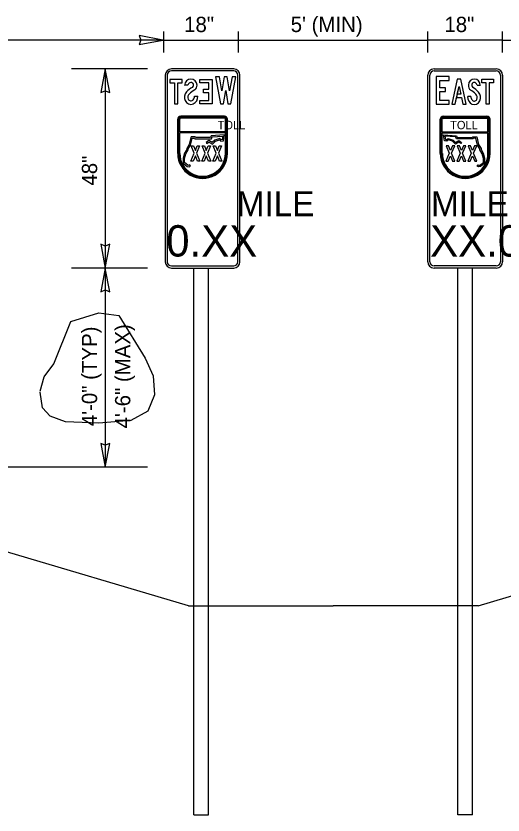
# Model space of a CAD drawing. Extents: x 56768 to 57406, y 11696 to 12105.
# Drawn here: x 56946.4 to 57035.7, y 11762.4 to 11908.9 of the extents above; entities that cross this region are included whole.
import ezdxf

# ---------------------------------------------------------------- set-up
doc = ezdxf.new("R2010")
doc.units = 0
for name, color, linetype in [('1', 7, 'Continuous'), ('52', 7, 'Continuous'), ('62', 7, 'Continuous'), ('DimLines_dp', 7, 'Continuous'), ('SignPanel', 7, 'Continuous'), ('XSGrdLine_ex', 7, 'Continuous')]:
    doc.layers.add(name, color=color, linetype=linetype)

msp = doc.modelspace()

# ---------------------------------------------------------------- linework, layer by layer
at = {"layer": '1'}
for p, q in [((56979.04, 11800.77), (56979.04, 11862.72)), ((56981.7, 11800.77), (56981.7, 11862.72)), ((57027.41, 11800.77), (57027.41, 11862.72)), ((57030.07, 11800.77), (57030.07, 11862.72)), ((56979.04, 11762.45), (56979.04, 11800.77)), ((56981.7, 11762.45), (56981.7, 11800.77)), ((57027.41, 11762.45), (57027.41, 11800.77)), ((57030.07, 11762.45), (57030.07, 11800.77)), ((56979.04, 11762.45), (56981.7, 11762.45)), ((57030.07, 11762.45), (57027.41, 11762.45))]:
    msp.add_line(p, q, dxfattribs=at)
at = {"layer": '52'}
msp.add_line((56970.53, 11826.22), (56892.41, 11826.22), dxfattribs=at)
at = {"layer": '62'}
msp.add_lwpolyline([(56950.87, 11840.16), (56951.57, 11842.76), (56953.37, 11845.17), (56956.48, 11852.92), (56961.58, 11854.52), (56965.28, 11854.02), (56970.08, 11846.17), (56971.58, 11842.96), (56971.78, 11839.46), (56970.58, 11836.46), (56967.48, 11834.75), (56961.58, 11834.25), (56955.47, 11834.55), (56952.67, 11835.56), (56951.27, 11837.06), (56950.87, 11839.96)], dxfattribs=at)
at = {"layer": 'DimLines_dp'}
for p, q in [((56973.53, 11902.22), (56973.53, 11906.05)), ((56987.21, 11902.22), (56987.21, 11906.05)), ((57021.89, 11902.22), (57021.89, 11906.05)), ((57035.58, 11902.22), (57035.58, 11906.05)), ((56973.53, 11904.5), (56892.41, 11904.5)), ((56973.34, 11904.5), (56968.99, 11905.34)), ((56968.99, 11905.34), (56969.32, 11904.5)), ((56969.32, 11904.5), (56968.99, 11903.69)), ((56968.99, 11903.69), (56973.34, 11904.5)), ((56973.53, 11904.5), (56987.21, 11904.5)), ((56987.21, 11904.5), (57021.89, 11904.5)), ((57035.58, 11904.5), (57021.89, 11904.5)), ((57035.58, 11904.5), (57116.7, 11904.5)), ((56970.53, 11899.22), (56956.6, 11899.22)), ((56962.78, 11899.22), (56961.94, 11894.87)), ((56962.78, 11899.22), (56962.78, 11862.72)), ((56963.59, 11894.87), (56962.78, 11899.22)), ((56961.94, 11894.87), (56962.78, 11895.2)), ((56962.78, 11895.2), (56963.59, 11894.87)), ((56962.78, 11866.74), (56961.97, 11867.07)), ((56961.97, 11867.07), (56962.78, 11862.72)), ((56962.78, 11866.74), (56961.97, 11867.07)), ((56961.97, 11867.07), (56962.78, 11862.72)), ((56962.78, 11862.72), (56963.62, 11867.07)), ((56963.62, 11867.07), (56962.78, 11866.74)), ((56962.78, 11862.72), (56963.62, 11867.07)), ((56963.62, 11867.07), (56962.78, 11866.74)), ((56970.53, 11862.72), (56956.6, 11862.72)), ((56962.78, 11862.72), (56961.94, 11858.37)), ((56962.78, 11862.72), (56962.78, 11826.22)), ((56963.59, 11858.37), (56962.78, 11862.72)), ((56961.94, 11858.37), (56962.78, 11858.7)), ((56962.78, 11858.7), (56963.59, 11858.37)), ((56962.78, 11830.24), (56961.97, 11830.57)), ((56961.97, 11830.57), (56962.78, 11826.22)), ((56962.78, 11826.22), (56963.62, 11830.57)), ((56963.62, 11830.57), (56962.78, 11830.24))]:
    msp.add_line(p, q, dxfattribs=at)
at = {"layer": 'SignPanel'}
for p, q in [((56977.92, 11896.21), (56977.31, 11896.21)), ((56977.92, 11896.21), (56977.31, 11896.21)), ((56977.92, 11896.21), (56977.31, 11896.21)), ((57030.93, 11896.21), (57031.52, 11896.21)), ((57030.93, 11896.21), (57031.52, 11896.21)), ((57030.93, 11896.21), (57031.52, 11896.21)), ((56979.12, 11894.2), (56979.74, 11894.2)), ((56979.12, 11894.2), (56979.74, 11894.2)), ((56979.12, 11894.2), (56979.74, 11894.2)), ((57029.79, 11894.17), (57029.2, 11894.17)), ((57029.79, 11894.17), (57029.2, 11894.17)), ((57029.79, 11894.17), (57029.2, 11894.17)), ((56976.05, 11883.7), (56976.05, 11889.98)), ((56976.25, 11883.7), (56976.25, 11889.98)), ((56976.44, 11887.7), (56976.44, 11889.98)), ((56984.61, 11890.55), (56976.62, 11890.55)), ((56984.61, 11890.36), (56976.62, 11890.36)), ((56984.61, 11890.17), (56976.62, 11890.17)), ((56984.8, 11887.7), (56984.8, 11889.98)), ((56984.99, 11883.7), (56984.99, 11889.98)), ((56985.18, 11883.7), (56985.18, 11889.98)), ((57024.18, 11883.7), (57024.18, 11889.98)), ((57024.37, 11883.7), (57024.37, 11889.98)), ((57024.55, 11887.7), (57024.55, 11889.98)), ((57024.75, 11890.55), (57032.73, 11890.55)), ((57024.75, 11890.36), (57032.73, 11890.36)), ((57024.75, 11890.17), (57032.73, 11890.17)), ((57032.92, 11887.7), (57032.92, 11889.98)), ((57033.11, 11883.7), (57033.11, 11889.98)), ((57033.3, 11883.7), (57033.3, 11889.98)), ((56984.8, 11887.7), (56976.44, 11887.7)), ((56976.44, 11883.7), (56976.44, 11887.51)), ((56984.8, 11887.51), (56976.44, 11887.51)), ((56978.5, 11886.77), (56978.17, 11885.34)), ((56979.24, 11886.77), (56978.5, 11886.77)), ((56979.34, 11886.62), (56979.24, 11886.77)), ((56982.07, 11886.62), (56979.34, 11886.62)), ((56982.21, 11886.96), (56982.07, 11886.62)), ((56984.59, 11887.14), (56982.21, 11886.96)), ((56982.23, 11886.39), (56982.37, 11886.74)), ((56982.37, 11886.74), (56984.31, 11886.89)), ((56983.33, 11886.8), (56983.33, 11886.8)), ((56984.31, 11886.89), (56984.22, 11886.26)), ((56984.42, 11886.05), (56984.59, 11887.14)), ((56984.8, 11883.7), (56984.8, 11887.51)), ((57024.55, 11887.7), (57032.92, 11887.7)), ((57024.55, 11883.7), (57024.55, 11887.51)), ((57024.55, 11887.51), (57032.92, 11887.51)), ((57024.94, 11886.05), (57024.77, 11887.14)), ((57024.77, 11887.14), (57027.15, 11886.96)), ((57026.99, 11886.74), (57025.04, 11886.89)), ((57025.04, 11886.89), (57025.14, 11886.26)), ((57026.03, 11886.8), (57026.03, 11886.8)), ((57027.13, 11886.39), (57026.99, 11886.74)), ((57027.15, 11886.96), (57027.28, 11886.62)), ((57027.28, 11886.62), (57030.01, 11886.62)), ((57030.01, 11886.62), (57030.12, 11886.77)), ((57030.12, 11886.77), (57030.85, 11886.77)), ((57030.85, 11886.77), (57031.18, 11885.34)), ((57032.92, 11883.7), (57032.92, 11887.51)), ((56978.17, 11885.34), (56977.72, 11884.61)), ((56977.95, 11884.54), (56978.39, 11885.25)), ((56978.39, 11885.25), (56978.69, 11886.54)), ((56978.69, 11886.54), (56979.12, 11886.54)), ((56979.12, 11886.54), (56979.22, 11886.39)), ((56979.22, 11886.39), (56982.23, 11886.39)), ((56981.78, 11886.09), (56981.28, 11885.75)), ((56981.28, 11885.75), (56981.41, 11885.56)), ((56981.41, 11885.56), (56981.79, 11885.82)), ((56982.39, 11885.73), (56981.78, 11886.09)), ((56981.79, 11885.82), (56982.42, 11885.45)), ((56982.84, 11886.15), (56982.39, 11885.73)), ((56982.42, 11885.45), (56982.96, 11885.95)), ((56983.76, 11886.45), (56982.84, 11886.15)), ((56982.96, 11885.95), (56983.71, 11886.19)), ((56983.71, 11886.19), (56983.96, 11886)), ((56984.03, 11886.24), (56983.76, 11886.45)), ((56983.96, 11886), (56984.42, 11886.05)), ((56984.22, 11886.26), (56984.03, 11886.24)), ((57025.39, 11886), (57024.94, 11886.05)), ((57025.14, 11886.26), (57025.33, 11886.24)), ((57025.33, 11886.24), (57025.6, 11886.45)), ((57025.64, 11886.19), (57025.39, 11886)), ((57025.6, 11886.45), (57026.52, 11886.15)), ((57026.4, 11885.95), (57025.64, 11886.19)), ((57026.94, 11885.45), (57026.4, 11885.95)), ((57026.52, 11886.15), (57026.97, 11885.73)), ((57027.57, 11885.82), (57026.94, 11885.45)), ((57026.97, 11885.73), (57027.58, 11886.09)), ((57030.14, 11886.39), (57027.13, 11886.39)), ((57027.95, 11885.56), (57027.57, 11885.82)), ((57027.58, 11886.09), (57028.08, 11885.75)), ((57028.08, 11885.75), (57027.95, 11885.56)), ((57030.24, 11886.54), (57030.14, 11886.39)), ((57030.67, 11886.54), (57030.24, 11886.54)), ((57030.97, 11885.25), (57030.67, 11886.54)), ((57031.41, 11884.54), (57030.97, 11885.25)), ((57031.18, 11885.34), (57031.64, 11884.61)), ((56977.31, 11883.75), (56977.06, 11882.83)), ((56977.29, 11882.8), (56977.52, 11883.66)), ((56977.72, 11884.43), (56977.31, 11883.75)), ((56977.52, 11883.66), (56977.95, 11884.36)), ((56977.72, 11884.61), (56977.72, 11884.43)), ((56977.95, 11884.36), (56977.95, 11884.54)), ((57031.41, 11884.36), (57031.41, 11884.54)), ((57031.83, 11883.66), (57031.41, 11884.36)), ((57031.64, 11884.61), (57031.64, 11884.43)), ((57031.64, 11884.43), (57032.05, 11883.75)), ((57032.07, 11882.8), (57031.83, 11883.66)), ((57032.05, 11883.75), (57032.3, 11882.83)), ((56977.06, 11882.83), (56977.06, 11881.97)), ((56977.29, 11882.07), (56977.29, 11882.8)), ((57032.07, 11882.07), (57032.07, 11882.8)), ((57032.3, 11882.83), (57032.3, 11881.97)), ((56977.06, 11881.97), (56977.81, 11881.35)), ((56977.91, 11881.56), (56977.29, 11882.07)), ((56977.81, 11881.35), (56978.17, 11881.26)), ((56978.12, 11881.51), (56977.91, 11881.56)), ((56978.26, 11881.61), (56978.12, 11881.51)), ((56978.17, 11881.26), (56978.39, 11881.42)), ((56978.39, 11881.42), (56978.26, 11881.61)), ((57030.96, 11881.42), (57031.09, 11881.61)), ((57031.19, 11881.26), (57030.96, 11881.42)), ((57031.09, 11881.61), (57031.24, 11881.51)), ((57031.55, 11881.35), (57031.19, 11881.26)), ((57031.24, 11881.51), (57031.44, 11881.56)), ((57031.44, 11881.56), (57032.07, 11882.07)), ((57032.3, 11881.97), (57031.55, 11881.35))]:
    msp.add_line(p, q, dxfattribs=at)
for points in [[(56986.32, 11899.22), (56974.91, 11899.22)], [(56986.32, 11898.84), (56974.91, 11898.84)], [(57023.03, 11899.22), (57034.44, 11899.22)], [(57023.03, 11898.84), (57034.44, 11898.84)], [(56973.77, 11898.08), (56973.77, 11863.86)], [(56974.15, 11898.08), (56974.15, 11863.86)], [(56987.08, 11863.86), (56987.08, 11898.08)], [(56987.46, 11863.86), (56987.46, 11898.08)], [(57021.89, 11863.86), (57021.89, 11898.08)], [(57022.27, 11863.86), (57022.27, 11898.08)], [(57035.2, 11898.08), (57035.2, 11863.86)], [(57035.58, 11898.08), (57035.58, 11863.86)], [(56974.91, 11863.1), (56986.32, 11863.1)], [(56974.91, 11862.72), (56986.32, 11862.72)], [(57034.44, 11863.1), (57023.03, 11863.1)], [(57034.44, 11862.72), (57023.03, 11862.72)]]:
    msp.add_lwpolyline(points, dxfattribs=at)
for points in [[(56976.06, 11896.66), (56976.88, 11896.66), (56976.88, 11897.29), (56974.62, 11897.29), (56974.62, 11896.66), (56975.44, 11896.66), (56975.44, 11892.79), (56976.06, 11892.79)], [(56976.06, 11896.66), (56976.88, 11896.66), (56976.88, 11897.29), (56974.62, 11897.29), (56974.62, 11896.66), (56975.44, 11896.66), (56975.44, 11892.79), (56976.06, 11892.79)], [(56976.06, 11896.66), (56976.88, 11896.66), (56976.88, 11897.29), (56974.62, 11897.29), (56974.62, 11896.66), (56975.44, 11896.66), (56975.44, 11892.79), (56976.06, 11892.79)], [(56981.77, 11893.42), (56981.77, 11894.86), (56980.8, 11894.86), (56980.8, 11895.49), (56981.77, 11895.49), (56981.77, 11896.66), (56980.13, 11896.66), (56980.13, 11897.29), (56982.39, 11897.29), (56982.39, 11892.79), (56980.13, 11892.79), (56980.13, 11893.42)], [(56981.77, 11893.42), (56981.77, 11894.86), (56980.8, 11894.86), (56980.8, 11895.49), (56981.77, 11895.49), (56981.77, 11896.66), (56980.13, 11896.66), (56980.13, 11897.29), (56982.39, 11897.29), (56982.39, 11892.79), (56980.13, 11892.79), (56980.13, 11893.42)], [(56981.77, 11893.42), (56981.77, 11894.86), (56980.8, 11894.86), (56980.8, 11895.49), (56981.77, 11895.49), (56981.77, 11896.66), (56980.13, 11896.66), (56980.13, 11897.29), (56982.39, 11897.29), (56982.39, 11892.79), (56980.13, 11892.79), (56980.13, 11893.42)], [(56985.55, 11895.18), (56985.15, 11897.74), (56984.55, 11897.74), (56984.14, 11895.18), (56983.69, 11897.74), (56982.99, 11897.74), (56983.87, 11892.79), (56984.46, 11892.79), (56984.85, 11895.27), (56985.24, 11892.79), (56985.82, 11892.79), (56986.7, 11897.74), (56986.01, 11897.74)], [(56985.55, 11895.18), (56985.15, 11897.74), (56984.55, 11897.74), (56984.14, 11895.18), (56983.69, 11897.74), (56982.99, 11897.74), (56983.87, 11892.79), (56984.46, 11892.79), (56984.85, 11895.27), (56985.24, 11892.79), (56985.82, 11892.79), (56986.7, 11897.74), (56986.01, 11897.74)], [(56985.55, 11895.18), (56985.15, 11897.74), (56984.55, 11897.74), (56984.14, 11895.18), (56983.69, 11897.74), (56982.99, 11897.74), (56983.87, 11892.79), (56984.46, 11892.79), (56984.85, 11895.27), (56985.24, 11892.79), (56985.82, 11892.79), (56986.7, 11897.74), (56986.01, 11897.74)], [(57024.1, 11893.44), (57024.1, 11895.07), (57025.12, 11895.07), (57025.12, 11895.77), (57024.1, 11895.77), (57024.1, 11897.09), (57025.82, 11897.09), (57025.82, 11897.8), (57023.45, 11897.8), (57023.45, 11892.74), (57025.82, 11892.74), (57025.82, 11893.44)], [(57024.1, 11893.44), (57024.1, 11895.07), (57025.12, 11895.07), (57025.12, 11895.77), (57024.1, 11895.77), (57024.1, 11897.09), (57025.82, 11897.09), (57025.82, 11897.8), (57023.45, 11897.8), (57023.45, 11892.74), (57025.82, 11892.74), (57025.82, 11893.44)], [(57024.1, 11893.44), (57024.1, 11895.07), (57025.12, 11895.07), (57025.12, 11895.77), (57024.1, 11895.77), (57024.1, 11897.09), (57025.82, 11897.09), (57025.82, 11897.8), (57023.45, 11897.8), (57023.45, 11892.74), (57025.82, 11892.74), (57025.82, 11893.44)], [(57028.07, 11893.96), (57028.34, 11892.74), (57028.95, 11892.74), (57027.93, 11897.31), (57027.29, 11897.31), (57026.27, 11892.74), (57026.88, 11892.74), (57027.15, 11893.96)], [(57027.3, 11894.6), (57027.15, 11893.96), (57028.07, 11893.96), (57028.34, 11892.74), (57028.95, 11892.74), (57027.93, 11897.31), (57027.29, 11897.31), (57026.27, 11892.74), (57026.88, 11892.74), (57027.61, 11896.01), (57027.92, 11894.6)], [(57027.3, 11894.6), (57027.15, 11893.96), (57028.07, 11893.96), (57028.34, 11892.74), (57028.95, 11892.74), (57027.93, 11897.31), (57027.29, 11897.31), (57026.27, 11892.74), (57026.88, 11892.74), (57027.61, 11896.01), (57027.92, 11894.6)], [(57032.58, 11896.67), (57031.8, 11896.67), (57031.8, 11897.31), (57033.94, 11897.31), (57033.94, 11896.67), (57033.16, 11896.67), (57033.16, 11892.74), (57032.58, 11892.74)], [(57032.58, 11896.67), (57031.8, 11896.67), (57031.8, 11897.31), (57033.94, 11897.31), (57033.94, 11896.67), (57033.16, 11896.67), (57033.16, 11892.74), (57032.58, 11892.74)], [(57032.58, 11896.67), (57031.8, 11896.67), (57031.8, 11897.31), (57033.94, 11897.31), (57033.94, 11896.67), (57033.16, 11896.67), (57033.16, 11892.74), (57032.58, 11892.74)], [(57027.61, 11896.01), (57027.92, 11894.6), (57027.3, 11894.6)], [(56979.7, 11882.29), (56979.29, 11883.26), (56978.88, 11882.29), (56978.45, 11882.29), (56979.07, 11883.77), (56978.5, 11885.14), (56978.93, 11885.14), (56979.29, 11884.28), (56979.65, 11885.14), (56980.07, 11885.14), (56979.5, 11883.77), (56980.12, 11882.29)], [(56981.71, 11882.29), (56981.3, 11883.26), (56980.9, 11882.29), (56980.47, 11882.29), (56981.09, 11883.77), (56980.52, 11885.14), (56980.95, 11885.14), (56981.3, 11884.28), (56981.66, 11885.14), (56982.09, 11885.14), (56981.52, 11883.77), (56982.14, 11882.29)], [(56983.73, 11882.29), (56983.32, 11883.26), (56982.91, 11882.29), (56982.48, 11882.29), (56983.11, 11883.77), (56982.53, 11885.14), (56982.96, 11885.14), (56983.32, 11884.28), (56983.68, 11885.14), (56984.11, 11885.14), (56983.53, 11883.77), (56984.16, 11882.29)], [(57025.63, 11882.29), (57026.04, 11883.26), (57026.44, 11882.29), (57026.87, 11882.29), (57026.25, 11883.77), (57026.82, 11885.14), (57026.39, 11885.14), (57026.04, 11884.28), (57025.68, 11885.14), (57025.25, 11885.14), (57025.82, 11883.77), (57025.2, 11882.29)], [(57027.64, 11882.29), (57028.05, 11883.26), (57028.46, 11882.29), (57028.89, 11882.29), (57028.27, 11883.77), (57028.84, 11885.14), (57028.41, 11885.14), (57028.05, 11884.28), (57027.69, 11885.14), (57027.27, 11885.14), (57027.84, 11883.77), (57027.22, 11882.29)], [(57029.66, 11882.29), (57030.07, 11883.26), (57030.48, 11882.29), (57030.9, 11882.29), (57030.28, 11883.77), (57030.85, 11885.14), (57030.43, 11885.14), (57030.07, 11884.28), (57029.71, 11885.14), (57029.28, 11885.14), (57029.85, 11883.77), (57029.23, 11882.29)]]:
    msp.add_lwpolyline(points, close=True, dxfattribs=at)
for centre, radius, start, end in [((56974.91, 11898.08), 1.14, 90, 180), ((56974.91, 11898.08), 0.76, 90, 180), ((56986.32, 11898.08), 1.14, 0, 90), ((56986.32, 11898.08), 0.76, 0, 90), ((57023.03, 11898.08), 1.14, 90, 180), ((57023.03, 11898.08), 0.76, 90, 180), ((57034.44, 11898.08), 1.14, 0, 90), ((57034.44, 11898.08), 0.76, 0, 90), ((56974.91, 11863.86), 1.14, 180, 270), ((56974.91, 11863.86), 0.76, 180, 270), ((56986.32, 11863.86), 1.14, 270, 0), ((56986.32, 11863.86), 0.76, 270, 0), ((57023.03, 11863.86), 1.14, 180, 270), ((57023.03, 11863.86), 0.76, 180, 270), ((57034.44, 11863.86), 1.14, 270, 360), ((57034.44, 11863.86), 0.76, 270, 360)]:
    msp.add_arc(centre, radius, start, end, dxfattribs=at)
for centre, major_axis, ratio, start_param, end_param in [((56978.46, 11896.18), (0, -1.17), 0.981197, 1.634182, 4.688511), ((56978.46, 11896.18), (0, -1.17), 0.981197, 1.634182, 4.688511), ((56978.46, 11896.18), (0, -1.17), 0.981197, 1.634182, 4.688511), ((57030.42, 11896.18), (0, 1.19), 0.91923, 4.736267, 7.790596), ((57030.42, 11896.18), (0, 1.19), 0.91923, 4.736267, 7.790596), ((57030.42, 11896.18), (0, 1.19), 0.91923, 4.736267, 7.790596), ((56980.77, 11892.05), (0, -4.32), 0.981197, 3.642536, 3.961892), ((56980.77, 11892.05), (0, -4.32), 0.981197, 3.642536, 3.961892), ((56980.77, 11892.05), (0, -4.32), 0.981197, 3.642536, 3.961892), ((56978.46, 11896.17), (0, -0.55), 0.981197, 2.28404, 4.637874), ((56978.46, 11896.17), (0, -0.55), 0.981197, 2.28404, 4.637874), ((56978.46, 11896.17), (0, -0.55), 0.981197, 2.28404, 4.637874), ((56981.31, 11891.36), (0, -4.56), 0.981197, 3.63779, 3.909641), ((56981.31, 11891.36), (0, -4.56), 0.981197, 3.63779, 3.909641), ((56981.31, 11891.36), (0, -4.56), 0.981197, 3.63779, 3.909641), ((56978.53, 11896.24), (0, -0.453), 0.981197, 0.484634, 2.267813), ((56978.53, 11896.24), (0, -0.453), 0.981197, 0.484634, 2.267813), ((56978.53, 11896.24), (0, -0.453), 0.981197, 0.484634, 2.267813), ((56978.57, 11896.22), (0, -1.05), 0.981197, 0.629826, 1.606762), ((56978.57, 11896.22), (0, -1.05), 0.981197, 0.629826, 1.606762), ((56978.57, 11896.22), (0, -1.05), 0.981197, 0.629826, 1.606762), ((57030.31, 11896.22), (0, 1.07), 0.91923, 1.534831, 2.511766), ((57030.31, 11896.22), (0, 1.07), 0.91923, 1.534831, 2.511766), ((57030.31, 11896.22), (0, 1.07), 0.91923, 1.534831, 2.511766), ((57027.71, 11891.28), (0, 4.63), 0.91923, 5.515137, 5.786988), ((57027.71, 11891.28), (0, 4.63), 0.91923, 5.515137, 5.786988), ((57027.71, 11891.28), (0, 4.63), 0.91923, 5.515137, 5.786988), ((57030.35, 11896.24), (0, 0.46), 0.91923, 0.87378, 2.656959), ((57030.35, 11896.24), (0, 0.46), 0.91923, 0.87378, 2.656959), ((57030.35, 11896.24), (0, 0.46), 0.91923, 0.87378, 2.656959), ((57030.42, 11896.17), (0, 0.558), 0.91923, 4.786904, 7.140738), ((57030.42, 11896.17), (0, 0.558), 0.91923, 4.786904, 7.140738), ((57030.42, 11896.17), (0, 0.558), 0.91923, 4.786904, 7.140738), ((57028.22, 11891.98), (0, 4.39), 0.91923, 5.462886, 5.782242), ((57028.22, 11891.98), (0, 4.39), 0.91923, 5.462886, 5.782242), ((57028.22, 11891.98), (0, 4.39), 0.91923, 5.462886, 5.782242), ((56978.65, 11894.02), (0, -1.4), 0.981197, 3.939023, 5.163791), ((56978.65, 11894.02), (0, -1.4), 0.981197, 3.939023, 5.163791), ((56978.65, 11894.02), (0, -1.4), 0.981197, 3.939023, 5.163791), ((56978.66, 11894.02), (0, -0.78), 0.981197, 3.79238, 5.170369), ((56978.66, 11894.02), (0, -0.78), 0.981197, 3.79238, 5.170369), ((56978.66, 11894.02), (0, -0.78), 0.981197, 3.79238, 5.170369), ((56978.24, 11894.16), (0, -0.897), 0.981197, 0.859453, 1.616836), ((56978.3, 11894.14), (0, -1.47), 0.981197, 0.439911, 1.615229), ((56978.24, 11894.16), (0, -0.897), 0.981197, 0.859453, 1.616836), ((56978.3, 11894.14), (0, -1.47), 0.981197, 0.439911, 1.615229), ((56978.24, 11894.16), (0, -0.897), 0.981197, 0.859453, 1.616836), ((56978.3, 11894.14), (0, -1.47), 0.981197, 0.439911, 1.615229), ((57030.57, 11894.1), (0, 1.5), 0.91923, 1.526364, 2.701682), ((57030.57, 11894.1), (0, 1.5), 0.91923, 1.526364, 2.701682), ((57030.57, 11894.1), (0, 1.5), 0.91923, 1.526364, 2.701682), ((57030.63, 11894.13), (0, 0.911), 0.91923, 1.524757, 2.28214), ((57030.63, 11894.13), (0, 0.911), 0.91923, 1.524757, 2.28214), ((57030.63, 11894.13), (0, 0.911), 0.91923, 1.524757, 2.28214), ((57030.23, 11893.99), (0, 0.792), 0.91923, 4.254409, 5.632398), ((57030.23, 11893.99), (0, 0.792), 0.91923, 4.254409, 5.632398), ((57030.23, 11893.99), (0, 0.792), 0.91923, 4.254409, 5.632398), ((57030.24, 11893.98), (0, 1.42), 0.91923, 4.260987, 5.485755), ((57030.24, 11893.98), (0, 1.42), 0.91923, 4.260987, 5.485755), ((57030.24, 11893.98), (0, 1.42), 0.91923, 4.260987, 5.485755), ((56978.5, 11893.95), (0, -1.23), 0.981197, 5.173086, 6.638731), ((56978.5, 11893.95), (0, -1.23), 0.981197, 5.173086, 6.638731), ((56978.5, 11893.95), (0, -1.23), 0.981197, 5.173086, 6.638731), ((56978.47, 11893.94), (0, -0.572), 0.981197, 5.194718, 7.162991), ((56978.47, 11893.94), (0, -0.572), 0.981197, 5.194718, 7.162991), ((56978.47, 11893.94), (0, -0.572), 0.981197, 5.194718, 7.162991), ((57030.39, 11893.92), (0, 1.24), 0.91923, 2.786047, 4.251692), ((57030.39, 11893.92), (0, 1.24), 0.91923, 2.786047, 4.251692), ((57030.39, 11893.92), (0, 1.24), 0.91923, 2.786047, 4.251692), ((57030.41, 11893.9), (0, 0.581), 0.91923, 2.261787, 4.23006), ((57030.41, 11893.9), (0, 0.581), 0.91923, 2.261787, 4.23006), ((57030.41, 11893.9), (0, 0.581), 0.91923, 2.261787, 4.23006), ((56976.63, 11889.98), (0, 0.57), 0.9997, 0, 1.570796), ((56976.63, 11889.98), (0, 0.38), 0.9997, 0, 1.570796), ((56976.63, 11889.98), (0, 0.19), 0.9997, 0, 1.570796), ((56984.61, 11889.98), (0, 0.57), 0.9997, 4.712389, 6.283185), ((56984.61, 11889.98), (0, 0.38), 0.9997, 4.712389, 6.283185), ((56984.61, 11889.98), (0, 0.19), 0.9997, 4.712389, 6.283185), ((57024.75, 11889.98), (0, 0.57), 0.9997, 0, 1.570796), ((57024.75, 11889.98), (0, 0.38), 0.9997, 0, 1.570796), ((57024.75, 11889.98), (0, 0.19), 0.9997, 0, 1.570796), ((57032.73, 11889.98), (0, 0.57), 0.9997, 4.712389, 6.283185), ((57032.73, 11889.98), (0, 0.38), 0.9997, 4.712389, 6.283185), ((57032.73, 11889.98), (0, 0.19), 0.9997, 4.712389, 6.283185), ((56980.62, 11883.71), (0, 4.56), 0.9997, 1.570796, 4.712389), ((56980.62, 11883.71), (0, 4.37), 0.9997, 1.570796, 4.712389), ((56980.62, 11883.71), (0, 4.18), 0.9997, 1.570796, 4.712389), ((57028.74, 11883.71), (0, -4.56), 0.9997, 4.712389, 7.853982), ((57028.74, 11883.71), (0, -4.37), 0.9997, 4.712389, 7.853982), ((57028.74, 11883.71), (0, -4.18), 0.9997, 4.712389, 7.853982)]:
    msp.add_ellipse(centre, major_axis=major_axis, ratio=ratio, start_param=start_param, end_param=end_param, dxfattribs=at)
at = {"layer": 'XSGrdLine_ex'}
for p, q in [((56978.01, 11800.77), (56913.04, 11820.09)), ((57031.1, 11800.77), (57096.06, 11820.09)), ((56978.01, 11800.77), (57004.55, 11800.77)), ((57031.1, 11800.77), (57004.55, 11800.77))]:
    msp.add_line(p, q, dxfattribs=at)

# ---------------------------------------------------------------- texts
at = {"layer": 'DimLines_dp'}
for s, p in [('18"', (56977.23, 11905.97)), ("5' (MIN)", (56996.76, 11905.97)), ('18"', (57024.93, 11905.97))]:
    msp.add_text(s, height=2.8, dxfattribs=at).set_placement(p)
for s, p in [('48"', (56961.29, 11877.83)), ('4\'-0" (TYP)', (56961.29, 11833.72)), ('4\'-6" (MAX)', (56967.37, 11833.32))]:
    msp.add_text(s, height=2.8, rotation=90, dxfattribs=at).set_placement(p)
at = {"layer": 'SignPanel'}
for s, height, p in [('TOLL', 1.519, (56983.37, 11888.17)), ('TOLL', 1.519, (57025.98, 11888.17)), ('MILE', 4.562, (56986.87, 11872.22)), ('MILE', 4.562, (57022.48, 11872.22))]:
    msp.add_text(s, height=height, dxfattribs=at).set_placement(p)
for s, p in [('0.XX', (56973.95, 11864.82)), ('XX.0', (57022.32, 11864.82))]:
    msp.add_text(s, height=5.75, rotation=360, dxfattribs=at).set_placement(p)

doc.saveas('drawing.dxf')
